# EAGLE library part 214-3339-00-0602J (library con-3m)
Zero Insertion Force Socked Source: http://www.3M.com/ehpd
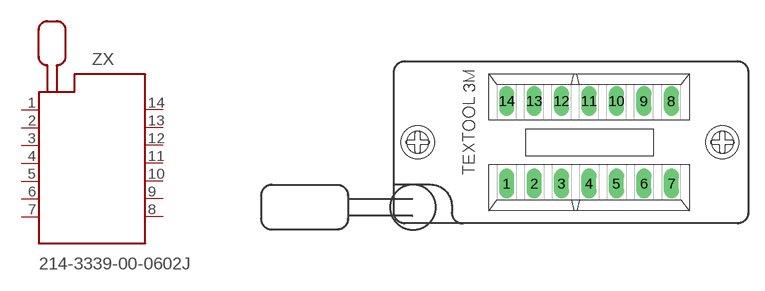
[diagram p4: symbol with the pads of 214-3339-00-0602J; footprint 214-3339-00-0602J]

Designator prefix ZX

## 214-3339-00-0602J (MF: 3M; MPN: 214-3339-00-0602J; OC_FARNELL: 1247151; OC_NEWARK: 85K7793)  [214-3339-00-0602J]
1  1  pas
2  2  pas
3  3  pas
4  4  pas
5  5  pas
6  6  pas
7  7  pas
8  8  pas
9  9  pas
10  10  pas
11  11  pas
12  12  pas
13  13  pas
14  14  pas

## Footprint 214-3339-00-0602J (pad centres in mm)
3M TEXTOOL 14 pol. DIP Lever actuated zero insertion force mechanism Hersteller: 3M TEXTOOL Herstellerbez.: 214-3339-00-0602J Farnell Best.-Nr.: 4666290 Source: http://www.3M.com/ehpd
drill 0.9 long: 1 -7.62,-3.81; 2 -5.08,-3.81; 3 -2.54,-3.81; 4 0,-3.81; 5 2.54,-3.81; 6 5.08,-3.81; 7 7.62,-3.81; 8 7.62,3.81; 9 5.08,3.81; 10 2.54,3.81; 11 0,3.81; 12 -2.54,3.81; 13 -5.08,3.81; 14 -7.62,3.81
hole 2 at 12.35,0
hole 2 at -15.85,0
